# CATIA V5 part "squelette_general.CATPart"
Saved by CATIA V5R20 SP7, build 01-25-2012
Part number: squelette_general
Publications: "Plan.zx", "Plan.yz", "Plan.xy", "K", "plan.bati", "F", "C", "machoires.a", "H", "plan.-2", "M", "G", "D", "Plan.2,1", "barre.DG", "E", "Abscisse.C", "Ordonnée.C", "Abscisse.K", "Ordonnée.K", "Abscisse.F", "Ordonnée.F", "Abscisse.a", "Ordonnée.a", "Longueur_GE", "Longueur_CK"
Bounding box of the stored display mesh (mm): x -4.1 to 2.1, y -58 to 18.5, z -9.5 to 59
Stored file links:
  F:\IAO\Catia\squelette_general.CATPart
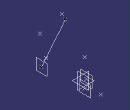
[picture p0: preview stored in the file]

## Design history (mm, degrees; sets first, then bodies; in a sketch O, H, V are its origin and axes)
Parameters
  Abscisse.C = -32 mm
  `Ordonnée.C` = 56.5 mm
  Abscisse.K = 0 mm
  `Ordonnée.K` = 0 mm
  Abscisse.F = 18.5 mm
  `Ordonnée.F` = -8.5 mm
  Abscisse.a = -58 mm
  `Ordonnée.a` = 22.5 mm
  Longueur_GE = 14.32 mm
  Longueur_CK = 64.933 mm
Point1 "K": (-4.1, 0 {= Abscisse.K}, 0 {= `Ordonnée.K`})
Point2 "H": (-2, 0, -9.5)
Point3 "C": type OnPlane, Support Plane4, H -32 {= Abscisse.C}, V 56.5 {= `Ordonnée.C`}, Direction (0, 1, 0)
Set1
  Plane1 "Plan.zx": type Offset, RefPlane zx-plane, Offset 0
  Plane2 "Plan.yz": type Offset, RefPlane yz-plane, Offset 0
  Plane3 "Plan.xy": type Offset, RefPlane xy-plane, Offset 0
  Plane4 "plan.bati": type OffsetPt, RefPlane Plane2, RefPoint Point1
  Point4 "F": type OnPlane, Support Plane4, H 18.5 {= Abscisse.F}, V -8.5 {= `Ordonnée.F`}, Direction (0, 1, 0)
  Point5 "machoires.a": (-2, -58 {= Abscisse.a}, 22.5 {= `Ordonnée.a`})
  Plane5 "plan.-2": type OffsetPt, RefPlane Plane2, RefPoint Point2
  Point6 "M": type OnPlane, Support Plane5, H 0, V 25.5, Direction (0, 1, 0)
  Point7 "G": (2.1, -52, -9.5)
  Plane6 "Plan.2,1": type OffsetPt, RefPlane Plane2, RefPoint Point7
  Point8 "D": type OnPlane, Support Plane6, H -21, V 59, Direction (0, 1, 0)
  Line1 "barre.DG": type PtPt, FirstPoint Point7, SecondPoint Point8
  Point9 "E": type OnCurve, Support Line1, RefPoint Point7, Length 14.32 {= Longueur_GE}
Body1 (main body)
